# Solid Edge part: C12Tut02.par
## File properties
Author: ASHUTOSH
Template: iso metric part.par
Last saved by: SOFT
Revision: 6
Application: Solid Edge
Accuracy: 0.990
Username: ASHUTOSH
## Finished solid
Body 1: solid body, 20 faces, 54 edges, 36 vertices.
  Faces by surface: plane 13, cylinder 7
  Edges by curve: line 40, circle 14
Bounding box of the edges (mm): 175.000 x 50.000 x 89.138, from (-48, -25, 0) to (127, 25, 89.1384).
Cylindrical faces by radius (mm): R5 x2, R6 x1, R9.7733 x1, R15 x2, R27 x1
Planar faces by outward normal: +y 3, +z 1, -y 3, -z 1, oblique 5
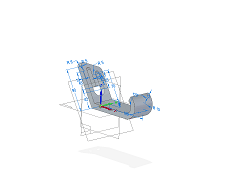
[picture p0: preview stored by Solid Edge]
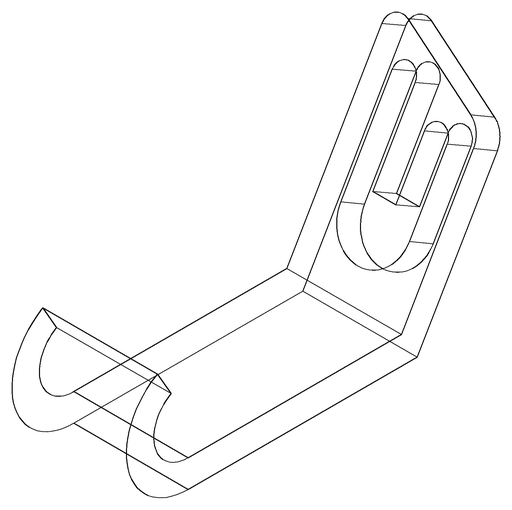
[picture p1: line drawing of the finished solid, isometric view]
